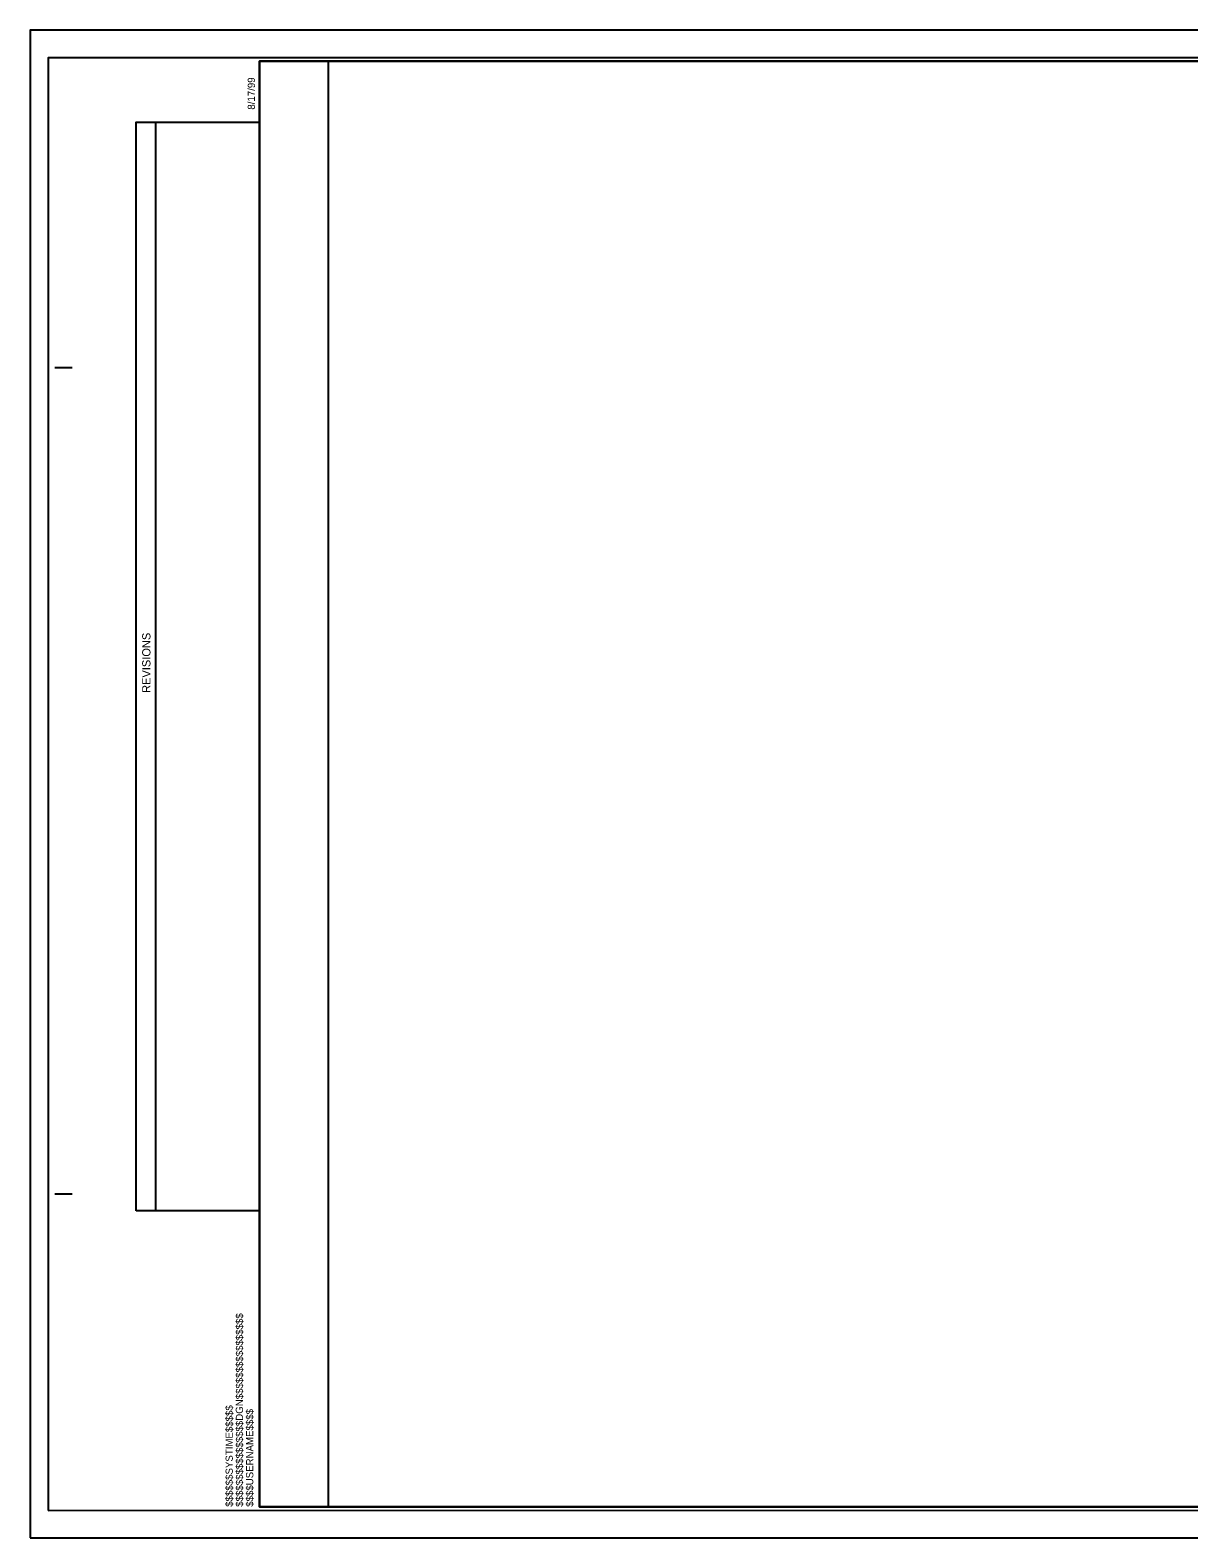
# Model space of a CAD drawing. Extents: x 2568837 to 2570520, y 536545 to 537640.
# Drawn here: x 2568837 to 2569678, y 536545 to 537640 of the extents above; entities that cross this region are included whole.
import ezdxf

# ---------------------------------------------------------------- set-up
doc = ezdxf.new("R2010")
doc.units = 0
for name, color, linetype in [('Sheet Block Revision CELL', 7, 'Continuous'), ('Sheet Clip Boundary CELL', 7, 'Continuous'), ('Sheet Cutting Line CELL', 7, 'Continuous'), ('Sheet Layout Plan Border', 7, 'Continuous'), ('Sheet Plan CELL', 7, 'Continuous'), ('Sheet Plan Layout CELL', 7, 'Continuous'), ('Sheet Plot Border Inside CELL', 7, 'Continuous'), ('Sheet Plot Border Outside CELL', 7, 'Continuous')]:
    doc.layers.add(name, color=color, linetype=linetype)

msp = doc.modelspace()

# ---------------------------------------------------------------- linework, layer by layer
at = {"layer": 'Sheet Block Revision CELL'}
msp.add_line((2568928.1, 536782.1), (2568928.1, 537572.7), dxfattribs=at)
msp.add_lwpolyline([(2568913.6, 536782.1), (2568913.6, 537572.7), (2569003.2, 537572.8), (2569003.2, 536782.1)], close=True, dxfattribs=at)
at = {"layer": 'Sheet Clip Boundary CELL'}
msp.add_lwpolyline([(2569053.2, 536567.2), (2570453.2, 536567.2), (2570453.2, 537405.7), (2570263.9, 537405.7), (2570263.9, 537617.2), (2569053.2, 537617.2)], close=True, dxfattribs=at)
at = {"layer": 'Sheet Cutting Line CELL'}
for p, q in [((2570520.2, 537639.6), (2568836.7, 537639.6)), ((2568836.7, 537639.6), (2568836.7, 536544.6)), ((2568836.7, 536544.6), (2570520.2, 536544.6))]:
    msp.add_line(p, q, dxfattribs=at)
at = {"layer": 'Sheet Layout Plan Border'}
msp.add_lwpolyline([(2569053.2, 536567.2), (2570453.2, 536567.2), (2570453.2, 537405.7), (2570263.9, 537405.7), (2570263.9, 537617.2), (2569053.2, 537617.2)], close=True, dxfattribs=at)
at = {"layer": 'Sheet Plan CELL'}
for p, q in [((2569003.2, 537617.2), (2569003.2, 537617.2)), ((2568854.7, 537394.6), (2568867.2, 537394.7)), ((2568854.7, 536794.6), (2568867.2, 536794.6)), ((2569003.2, 536567.2), (2569003.2, 536567.2))]:
    msp.add_line(p, q, dxfattribs=at)
for points in [[(2570503.2, 537617.2), (2569003.2, 537617.2), (2569003.2, 536567.2), (2570503.2, 536567.2)], [(2569003.2, 536567.2), (2569003.2, 537617.1), (2570303.1, 537617.2), (2570303.2, 537467.1), (2570503.2, 537467.1), (2570503.2, 536567.2)]]:
    msp.add_lwpolyline(points, close=True, dxfattribs=at)
at = {"layer": 'Sheet Plan Layout CELL'}
msp.add_lwpolyline([(2569003.2, 537617.1), (2569003.2, 536567.2), (2570503.2, 536567.2), (2570503.2, 537405.7), (2570263.9, 537405.7), (2570263.9, 537617.2)], close=True, dxfattribs=at)
at = {"layer": 'Sheet Plot Border Inside CELL'}
msp.add_lwpolyline([(2568849.7, 536564.6), (2570515.7, 536564.7), (2570515.7, 537619.6), (2568849.7, 537619.6)], close=True, dxfattribs=at)
at = {"layer": 'Sheet Plot Border Outside CELL'}
msp.add_lwpolyline([(2568836.7, 536544.6), (2570520.2, 536544.6), (2570520.2, 537639.6), (2568836.7, 537639.6)], close=True, dxfattribs=at)

# ---------------------------------------------------------------- texts
at = {"layer": 'Sheet Block Revision CELL'}
msp.add_text('REVISIONS', height=6, rotation=90, dxfattribs=at).set_placement((2568924.1, 537158.3))
at = {"layer": 'Sheet Plan CELL'}
for s, p in [('8/17/99', (2569000, 537581.9)), ('$$$$$$$$$$$$$$$$DGN$$$$$$$$$$$$$$$$', (2568991.3, 536567.2)), ('$$$$$$SYSTIME$$$$$', (2568983.9, 536567.2)), ('$$$$USERNAME$$$$', (2568998.8, 536567.2))]:
    msp.add_text(s, height=5.25, rotation=90, dxfattribs=at).set_placement(p)

doc.saveas('drawing.dxf')
